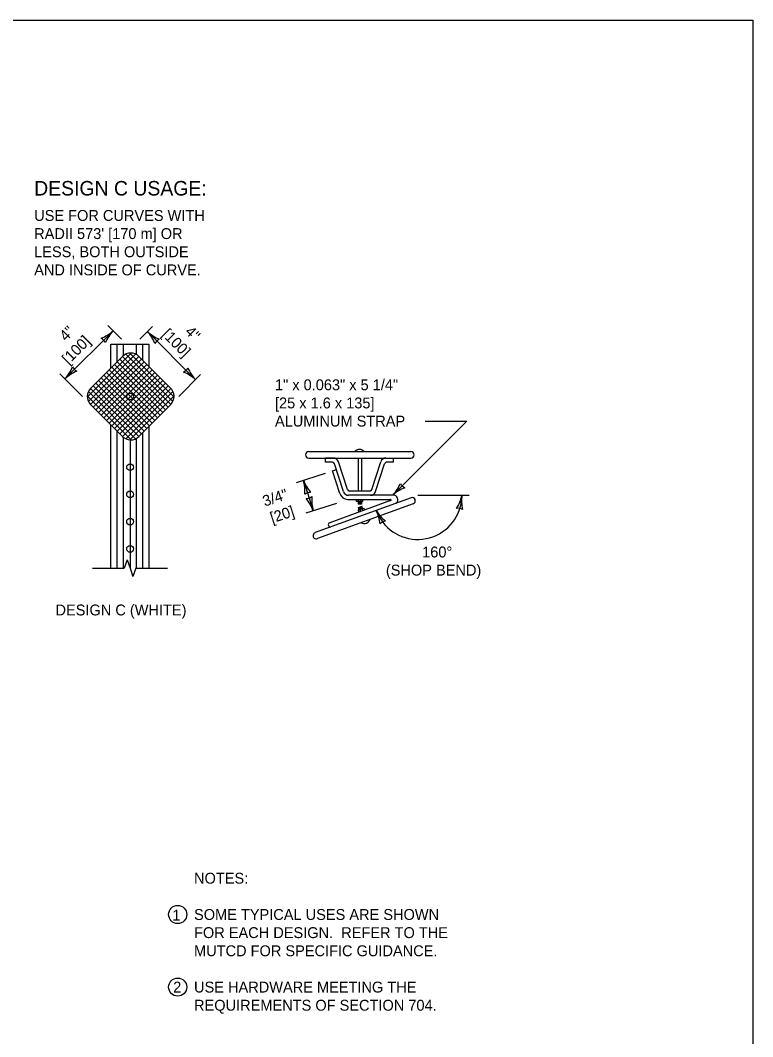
# Model space of a CAD drawing. Extents: x 49991.4 to 50021, y 49987.6 to 50011.4.
# Drawn here: x 50012.71 to 50016.75, y 49993.4 to 49999 of the extents above; entities that cross this region are included whole.
import ezdxf

# ---------------------------------------------------------------- set-up
doc = ezdxf.new("R2010")
doc.units = 0
for name, color, linetype in [('Level 1', 7, 'Continuous'), ('Level 2', 7, 'Continuous'), ('Level 3', 7, 'Continuous'), ('Level 5', 7, 'Continuous'), ('Level 6', 7, 'Continuous')]:
    doc.layers.add(name, color=color, linetype=linetype)

msp = doc.modelspace()

# ---------------------------------------------------------------- linework, layer by layer
at = {"layer": 'Level 1'}
for p, q in [((50013.2116, 49997.2147), (50013.4242, 49997.2147)), ((50013.2116, 49997.0819), (50013.2116, 49997.2147)), ((50013.2471, 49997.1174), (50013.2471, 49997.2147)), ((50013.2825, 49997.1523), (50013.2825, 49997.2147)), ((50013.3534, 49997.1572), (50013.3534, 49997.2147)), ((50013.3889, 49997.1244), (50013.3889, 49997.2147)), ((50013.4242, 49997.0891), (50013.4242, 49997.2147)), ((50013.0823, 49996.923), (50013.3251, 49997.1659)), ((50013.0883, 49996.8997), (50013.3484, 49997.1599)), ((50013.1005, 49996.8825), (50013.3657, 49997.1476)), ((50013.2762, 49997.1466), (50013.1005, 49996.9709)), ((50013.1152, 49996.8678), (50013.3804, 49997.1329)), ((50013.2623, 49997.1326), (50013.5275, 49996.8675)), ((50013.277, 49997.1473), (50013.5422, 49996.8822)), ((50013.2941, 49997.1597), (50013.5544, 49996.8994)), ((50013.3174, 49997.1658), (50013.5606, 49996.9226)), ((50013.5393, 49996.9738), (50013.3664, 49997.1469)), ((50013.1299, 49996.8531), (50013.395, 49997.1182)), ((50013.1446, 49996.8384), (50013.4097, 49997.1035)), ((50013.1594, 49996.8236), (50013.4244, 49997.0888)), ((50013.1741, 49996.8089), (50013.4391, 49997.0741)), ((50013.2035, 49997.0738), (50013.4686, 49996.8086)), ((50013.2182, 49997.0885), (50013.4833, 49996.8233)), ((50013.2329, 49997.1032), (50013.4981, 49996.8381)), ((50013.2476, 49997.1179), (50013.5128, 49996.8528)), ((50013.1594, 49997.0297), (50013.4245, 49996.7645)), ((50013.1741, 49997.0444), (50013.4392, 49996.7792)), ((50013.1888, 49996.7942), (50013.4538, 49997.0594)), ((50013.1888, 49997.0591), (50013.4539, 49996.7939)), ((50013.2035, 49996.7795), (50013.4685, 49997.0447)), ((50013.2182, 49996.7648), (50013.4832, 49997.03)), ((50013.1005, 49996.9708), (50013.3657, 49996.7057)), ((50013.1152, 49996.9856), (50013.3804, 49996.7204)), ((50013.1299, 49997.0003), (50013.3951, 49996.7351)), ((50013.1446, 49997.015), (50013.4098, 49996.7498)), ((50013.2329, 49996.7501), (50013.4979, 49997.0152)), ((50013.2476, 49996.7354), (50013.5127, 49997.0004)), ((50013.2623, 49996.7207), (50013.5274, 49996.9857)), ((50013.277, 49996.706), (50013.5422, 49996.9711)), ((50013.0823, 49996.9302), (50013.325, 49996.6875)), ((50013.0883, 49996.9536), (50013.3485, 49996.6935)), ((50013.2941, 49996.6937), (50013.5544, 49996.9541)), ((50013.3174, 49996.6875), (50013.5606, 49996.9308)), ((50013.1005, 49996.8825), (50013.2763, 49996.7067)), ((50013.366, 49996.7061), (50013.5424, 49996.8825)), ((50013.2116, 49995.98), (50013.2116, 49996.7714)), ((50013.4242, 49995.98), (50013.4242, 49996.7642)), ((50013.2471, 49995.98), (50013.2471, 49996.7359)), ((50013.2825, 49995.98), (50013.2825, 49996.7011)), ((50013.3534, 49995.98), (50013.3534, 49996.6962)), ((50013.3889, 49995.98), (50013.3889, 49996.7289)), ((50014.3037, 49996.6225), (50014.8662, 49996.6225)), ((50014.3037, 49996.5873), (50014.8662, 49996.5873)), ((50014.3958, 49996.5638), (50014.3958, 49996.5873)), ((50014.4385, 49996.5873), (50014.3958, 49996.5873)), ((50014.5752, 49996.5873), (50014.5752, 49996.4056)), ((50014.5947, 49996.5873), (50014.5947, 49996.4056)), ((50014.7282, 49996.5873), (50014.7709, 49996.5873)), ((50014.7709, 49996.5638), (50014.7709, 49996.5873)), ((50014.4341, 49996.5638), (50014.3958, 49996.5638)), ((50014.4332, 49996.5169), (50014.4555, 49996.5241)), ((50014.4738, 49996.3914), (50014.4332, 49996.5169)), ((50014.4948, 49996.4024), (50014.4453, 49996.5557)), ((50014.5158, 49996.4138), (50014.4662, 49996.5671)), ((50014.6509, 49996.4138), (50014.7003, 49996.5671)), ((50014.6719, 49996.4024), (50014.7214, 49996.5557)), ((50014.7709, 49996.5638), (50014.7325, 49996.5638)), ((50014.6397, 49996.4056), (50014.527, 49996.4056)), ((50014.867, 49996.3688), (50014.3384, 49996.1764)), ((50014.7542, 49996.3525), (50014.4185, 49996.2303)), ((50014.5182, 49996.3586), (50014.7531, 49996.3586)), ((50014.7665, 49996.3821), (50014.5226, 49996.3821)), ((50014.5663, 49996.3477), (50014.5663, 49996.3586)), ((50014.6018, 49996.3477), (50014.5663, 49996.3477)), ((50014.5752, 49996.3477), (50014.5752, 49996.333)), ((50014.5779, 49996.3477), (50014.5779, 49996.3586)), ((50014.5907, 49996.3477), (50014.5907, 49996.3586)), ((50014.5947, 49996.3477), (50014.5947, 49996.333)), ((50014.6018, 49996.3477), (50014.6018, 49996.3586)), ((50014.879, 49996.3357), (50014.3505, 49996.1433)), ((50014.5749, 49996.2994), (50014.6083, 49996.3115)), ((50014.5749, 49996.2994), (50014.5788, 49996.2887)), ((50014.5947, 49996.3402), (50014.5752, 49996.3402)), ((50014.5947, 49996.333), (50014.5752, 49996.333)), ((50014.5766, 49996.3156), (50014.5949, 49996.3223)), ((50014.5816, 49996.3019), (50014.5766, 49996.3156)), ((50014.5907, 49996.3437), (50014.5779, 49996.3437)), ((50014.5907, 49996.3368), (50014.5779, 49996.3368)), ((50014.579, 49996.3088), (50014.5973, 49996.3155)), ((50014.5816, 49996.3134), (50014.5937, 49996.3178)), ((50014.584, 49996.3069), (50014.596, 49996.3113)), ((50014.5854, 49996.3032), (50014.5892, 49996.2925)), ((50014.5999, 49996.3085), (50014.5949, 49996.3223)), ((50014.5973, 49996.3076), (50014.6013, 49996.2969)), ((50014.6083, 49996.3115), (50014.6122, 49996.3009))]:
    msp.add_line(p, q, dxfattribs=at)
msp.add_lwpolyline([(49999.3835, 49998.9992), (50016.7501, 49998.9992), (50016.7501, 49987.7988), (49999.3835, 49987.7988)], close=True, dxfattribs=at)
for centre in [(50013.319, 49996.9265), (50013.3186, 49996.537), (50013.3186, 49996.387), (50013.3186, 49996.2369), (50013.3186, 49996.0869)]:
    msp.add_circle(centre, 0.0188, dxfattribs=at)
for centre, radius, start, end in [((50013.3215, 49997.1035), 0.0625, 44.0788, 136.4048), ((50013.1447, 49996.9267), 0.0625, 135, 225), ((50013.4982, 49996.9267), 0.0625, 315, 48.9235), ((50013.3215, 49996.7499), 0.0625, 223.7651, 315.5114), ((50014.5832, 49996.6008), 0.034, 39.7949, 140.2051), ((50014.3037, 49996.6049), 0.0176, 90, 270), ((50014.4384, 49996.5581), 0.0293, 17.888, 90), ((50014.7281, 49996.5581), 0.0293, 90, 162.1111), ((50014.8662, 49996.6049), 0.0176, 270, 90), ((50014.4341, 49996.5521), 0.0117, 17.8891, 90), ((50014.7325, 49996.5521), 0.0117, 90, 162.1109), ((50014.5226, 49996.4114), 0.0293, 197.8891, 270), ((50014.527, 49996.4174), 0.0117, 197.8889, 270), ((50014.6397, 49996.4174), 0.0117, 270, 342.1111), ((50014.644, 49996.4114), 0.0293, 270, 342.1109), ((50014.5232, 49996.4119), 0.0536, 202.5254, 264.5679), ((50014.7536, 49996.3556), 0.0031, 280.2222, 100.2222), ((50014.7709, 49996.3587), 0.0239, 301.8038, 100.6049), ((50014.873, 49996.3522), 0.0176, 290, 110), ((50014.6089, 49996.2605), 0.034, 239.7949, 340.2051), ((50014.4225, 49996.2193), 0.0118, 109.8998, 279.8601), ((50014.3444, 49996.1598), 0.0176, 110, 290)]:
    msp.add_arc(centre, radius, start, end, dxfattribs=at)
at = {"layer": 'Level 2'}
for centre in [(50013.5808, 49994.0722), (50013.5808, 49993.6722)]:
    msp.add_circle(centre, 0.05, dxfattribs=at)
at = {"layer": 'Level 3'}
for p, q in [((50013.2705, 49997.243), (50013.1962, 49997.3171)), ((50013.442, 49997.3123), (50013.3727, 49997.243)), ((50012.9593, 49997.0237), (50013.2245, 49997.2889)), ((50013.4137, 49997.284), (50013.6789, 49997.0189)), ((50012.9311, 49997.052), (50013.0563, 49996.9267)), ((50013.5865, 49996.9266), (50013.7072, 49997.0472)), ((50014.7665, 49996.3821), (50015.1753, 49996.7909)), ((50014.9444, 49996.7909), (50015.1753, 49996.7909)), ((50014.2356, 49996.4532), (50014.3951, 49996.5046)), ((50014.2737, 49996.4655), (50014.3276, 49996.2972)), ((50014.9038, 49996.3821), (50015.1872, 49996.3821)), ((50014.2895, 49996.2849), (50014.4587, 49996.3394))]:
    msp.add_line(p, q, dxfattribs=at)
for centre, radius, start, end in [((50013.0739, 49997.4524), 0.2223, 292.456, 312.6395), ((50013.1338, 49997.1982), 0.0548, 27.1388, 62.8612), ((50013.3972, 49997.1324), 0.233, 137.8273, 157.0772), ((50013.2501, 49997.1334), 0.2223, 22.4668, 42.6503), ((50013.5701, 49997.4567), 0.233, 227.8381, 247.088), ((50013.5043, 49997.1934), 0.0548, 117.1496, 152.872), ((50012.7867, 49997.1801), 0.233, 317.8273, 337.0772), ((50013.05, 49997.1144), 0.0548, 207.1388, 242.8612), ((50013.5882, 49997.1096), 0.0548, 297.1496, 332.872), ((50013.8424, 49997.1696), 0.2223, 202.4668, 222.6503), ((50013.1099, 49996.8602), 0.2223, 112.456, 132.6395), ((50013.5225, 49996.8462), 0.233, 47.8381, 67.088), ((50014.0594, 49996.4064), 0.2223, 355.2143, 15.3978), ((50014.4918, 49996.5474), 0.233, 200.5856, 219.8354), ((50014.5938, 49996.5386), 0.233, 317.8273, 337.0772), ((50014.9171, 49996.2186), 0.2223, 112.456, 132.6395), ((50014.8571, 49996.4728), 0.0548, 207.1388, 242.8612), ((50014.3128, 49996.3434), 0.0548, 89.8971, 125.6194), ((50014.2885, 49996.4193), 0.0548, 269.8971, 305.6194), ((50014.1095, 49996.2152), 0.233, 20.5856, 39.8354), ((50014.542, 49996.3562), 0.2223, 175.2143, 195.3978), ((50014.9038, 49996.3821), 0.2434, 208.3046, 353.5925), ((50014.9295, 49996.4274), 0.2223, 328.078, 348.2615), ((50015.3786, 49996.3555), 0.233, 173.4493, 192.6992), ((50014.4756, 49996.2007), 0.2223, 6.0157, 26.1992), ((50014.8739, 49996.4202), 0.233, 211.387, 230.6369), ((50015.1263, 49996.2556), 0.0548, 62.7608, 98.4832), ((50014.7363, 49996.1863), 0.0548, 100.6985, 136.4209)]:
    msp.add_arc(centre, radius, start, end, dxfattribs=at)
at = {"layer": 'Level 5'}
msp.add_line((50013.3186, 49996.6875), (50013.3186, 49995.9781), dxfattribs=at)
at = {"layer": 'Level 6'}
for p, q in [((50013.3017, 49996.0257), (50013.2855, 49995.98)), ((50013.3017, 49996.0257), (50013.3179, 49995.98)), ((50013.1116, 49995.98), (50013.2855, 49995.98)), ((50013.3179, 49995.98), (50013.3341, 49995.9343)), ((50013.3503, 49995.98), (50013.3341, 49995.9343)), ((50013.3503, 49995.98), (50013.5242, 49995.98))]:
    msp.add_line(p, q, dxfattribs=at)

# ---------------------------------------------------------------- texts
at = {"layer": 'Level 2'}
for s, height, p in [('DESIGN C USAGE:', 0.08, (50012.7896, 49998.0339)), ('USE FOR CURVES WITH', 0.06, (50012.7896, 49997.894)), ("RADII 573' [170 m] OR ", 0.06, (50012.7896, 49997.794)), ('LESS, BOTH OUTSIDE ', 0.06, (50012.7896, 49997.694)), ('AND INSIDE OF CURVE.', 0.06, (50012.7896, 49997.594)), ('1" x 0.063" x 5 1/4"', 0.06, (50014.117, 49996.9609)), ('[25 x 1.6 x 135]', 0.06, (50014.117, 49996.8609)), ('ALUMINUM STRAP', 0.06, (50014.117, 49996.7609)), ('160°', 0.06, (50014.9282, 49996.0397)), ('(SHOP BEND)', 0.06, (50014.7282, 49995.9397)), ('DESIGN C (WHITE)', 0.06, (50012.9071, 49995.7201)), ('NOTES:', 0.06, (50013.6708, 49994.2422)), ('1', 0.06, (50013.5514, 49994.0387)), ('SOME TYPICAL USES ARE SHOWN', 0.06, (50013.6708, 49994.0422)), ('FOR EACH DESIGN.  REFER TO THE', 0.06, (50013.6708, 49993.9422)), ('MUTCD FOR SPECIFIC GUIDANCE.', 0.06, (50013.6708, 49993.8422)), ('2', 0.06, (50013.5557, 49993.6422)), ('USE HARDWARE MEETING THE ', 0.06, (50013.6708, 49993.6422)), ('REQUIREMENTS OF SECTION 704.', 0.06, (50013.6708, 49993.5422))]:
    msp.add_text(s, height=height, dxfattribs=at).set_placement(p)
for s, rotation, p in [('4"', 45, (50012.9645, 49997.2267)), ('[100]', 315, (50013.4896, 49997.2647)), ('4"', 315, (50013.6168, 49997.2789)), ('[100]', 45, (50012.9787, 49997.0996)), (' 3/4"', 17.8955, (50014.0389, 49996.3125)), ('[20]', 17.8955, (50014.1017, 49996.2277))]:
    msp.add_text(s, height=0.06, rotation=rotation, dxfattribs=at).set_placement(p)

doc.saveas('drawing.dxf')
